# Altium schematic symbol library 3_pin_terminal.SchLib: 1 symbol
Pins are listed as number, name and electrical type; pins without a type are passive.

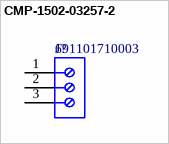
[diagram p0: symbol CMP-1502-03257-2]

## CMP-1502-03257-2
designator J?, comment 691101710003
NexarPartId: 8917705; Voltage Rating: 250V; Current: 16A; Wire Gauge (Min): 14AWG; Pitch: 5.0038mm; Wire Gauge (Max): 26AWG; Number of Positions Per Level: 3; Plating: Steel; Number of Levels: 1; Stripping Length: -7mm
footprint 691101710003 (5,00mm - modular - blue - Horizontal entry with pressure clamp - 12,6mm height - 03p)
pins: 1, 2, 3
